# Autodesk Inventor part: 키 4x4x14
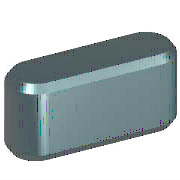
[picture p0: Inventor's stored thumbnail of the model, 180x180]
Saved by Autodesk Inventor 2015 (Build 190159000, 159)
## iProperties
IsCustomPart: 1
Created: 2012-02
Part Number: 키 4x4x14
Material: 강철, 연강
Description: 키 및 해당 키홈
Document SubType Name: Modeling
Standard: KS B 1311
Designer: mduedu
Standards Organization: KS
Language: ko-KR
Size Designation: 4 x 4 x 14
Categories: <MemberInstance><Categories><Category DisplayName="샤프트 부품" InternalName="7f7aeb1f-a693-4053-b835-cee3144e0d98" Mnemonic="SHFT"><Category DisplayName="키" Interna
Density: 1 g/cm^3
Appearance: 노란색
Author: mduedu
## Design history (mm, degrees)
workplane "Work Plane1"
workplane "Work Plane2"
sketch "스케치1"
  geometry: L1 (2, 2)-(12, 2); L2 (12, -2)-(2, -2); L3 (0, 9.4)-(0, -7.4) reference; L4 (-5, 0)-(30, 0) reference; L5 (14, 0)-(14, 7); A1 r 2 centre (2, 0) between (2, 2) and (2, -2); A2 r 2 centre (12, 0) between (12, -2) and (12, 2)
  constraints: 6 end point, 5 point on circle, 4 tangent, 3 point on line, 2 centre point, 1 horizontal, 1 parallel, 1 perpendicular
  dimensions: "d0" = 2 radius of A1 (= 0.5 x PB); "d13" = 2 radius of A2 (= 0.5 x PB); "d14" = 14 distance between parallel lines of L5 L3 (= NLG)
extrude "본체1" new body sketch "스케치1" taper "d3" = 0 deg; stored distance "d4" = 10
workplane "Work Plane3"
body "Solid1"
chamfer "모따기1" distance "d8" = 0.25 (= PHH); stored, may be unused: second distance "d9" = 0.25 (= PHH), angle "d15" = 45 deg
other parameters: "d1" = -2.5 (= -PNT), "d2" = 1.5 (= PH - PNT), "NLG" = 14 [user parameter; used in 3 equation terms], "PB" = 4 [user parameter; used in 2 equation terms], "PNT" = 2.5 [user parameter; used in 2 equation terms], "PH" = 4 [user parameter; used in 1 equation term], "PHH" = 0.25 [user parameter; used in 2 equation terms], "d10" = 0, "d16" = 0, "d17" = 0, "d18" = 0, "PLB2" = 14 (= NLG) [user parameter], "WDMAX" = 12 [user parameter], "PLB1" = 14 (= NLG) [user parameter], "RR" = 0.08 [user parameter], "PUEB" = 1.8 [user parameter]
